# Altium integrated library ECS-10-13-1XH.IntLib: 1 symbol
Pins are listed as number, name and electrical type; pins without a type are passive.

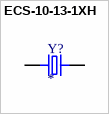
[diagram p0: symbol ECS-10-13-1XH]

## ECS-10-13-1XH
designator Y?
Crystal  HC49/U T/H; MP: ECS-10-13-1XH
footprint XTAL_ECS-10-13-1XH
pins: 1, 2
